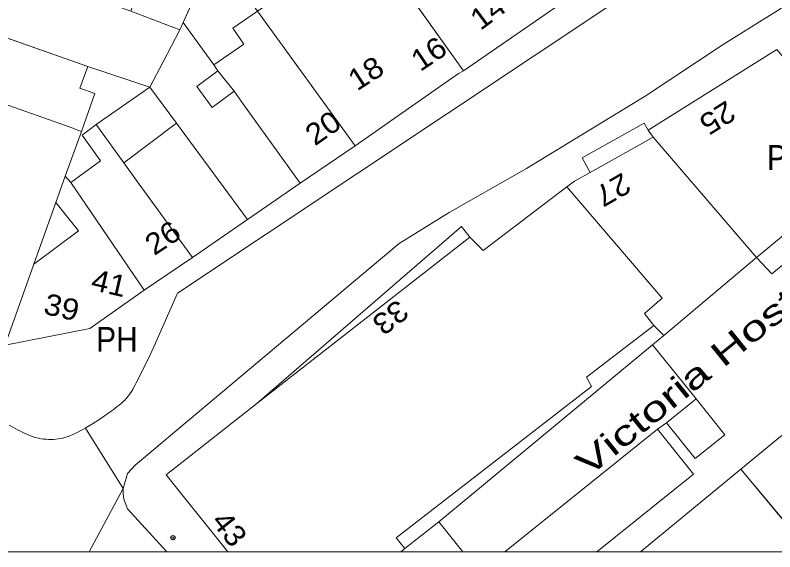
# Model space of a CAD drawing. Extents: x 528790 to 529292, y 179350 to 179856.
# Drawn here: x 529183.9 to 529237.6, y 179356 to 179393.9 of the extents above; entities that cross this region are included whole.
import ezdxf

# ---------------------------------------------------------------- set-up
doc = ezdxf.new("R2010")
doc.units = 0
doc.header["$LTSCALE"] = 0.6
doc.header["$PDMODE"] = 32
doc.header["$PDSIZE"] = 0.3
for name, color, linetype, lineweight in [('1', 7, 'Continuous', 13), ('2', 7, 'Continuous', 13), ('7', 7, 'Continuous', 13)]:
    doc.layers.add(name, color=color, linetype=linetype, lineweight=lineweight)
doc.layers.add('3', color=7, linetype='Continuous')
doc.layers.add('5', color=7, linetype='Continuous')

msp = doc.modelspace()

# ---------------------------------------------------------------- linework, layer by layer
at = {"layer": '1'}
for points in [[(529239.4, 179406.6), (529234.8, 179403.4), (529226.7, 179397.75), (529223, 179395.15), (529215.55, 179390), (529215.2, 179389.8), (529207.9, 179384.7), (529204, 179382.05), (529200.3, 179379.5), (529196.4, 179376.8), (529193, 179374.5), (529189.15, 179371.8), (529183.05, 179370.6)], [(529183.458, 179364.958), (529183.932, 179364.699), (529184.095, 179364.619), (529184.258, 179364.538), (529184.42, 179364.457), (529184.584, 179364.378), (529184.748, 179364.302), (529184.914, 179364.23), (529185.082, 179364.166), (529185.253, 179364.109), (529185.533, 179364.039), (529185.705, 179364.009), (529185.879, 179363.986), (529186.053, 179363.97), (529186.228, 179363.96), (529186.403, 179363.958), (529186.578, 179363.963), (529186.752, 179363.975), (529186.926, 179363.994), (529187.144, 179364.029), (529187.611, 179364.159), (529188.058, 179364.351), (529188.837, 179364.767), (529188.885, 179364.793), (529189.344, 179365.053), (529189.791, 179365.334), (529190.648, 179365.95), (529190.79, 179366.06), (529190.932, 179366.169), (529191.074, 179366.279), (529191.215, 179366.39), (529191.353, 179366.504), (529191.487, 179366.622), (529191.615, 179366.745), (529191.738, 179366.875), (529191.879, 179367.045), (529191.984, 179367.189), (529192.084, 179367.338), (529192.177, 179367.49), (529192.264, 179367.647), (529192.344, 179367.807), (529192.418, 179367.97), (529193.277, 179369.635), (529193.664, 179370.506), (529195.35, 179374.3), (529233.5, 179399.7)], [(529233.5, 179399.7), (529195.35, 179374.3), (529193.664, 179370.506), (529193.277, 179369.635), (529192.418, 179367.97), (529192.344, 179367.807), (529192.264, 179367.647), (529192.177, 179367.49), (529192.084, 179367.338), (529191.984, 179367.189), (529191.879, 179367.045), (529191.738, 179366.875), (529191.615, 179366.745), (529191.487, 179366.622), (529191.353, 179366.504), (529191.215, 179366.39), (529191.074, 179366.279), (529190.932, 179366.169), (529190.79, 179366.06), (529190.648, 179365.95), (529189.791, 179365.334), (529189.344, 179365.053), (529188.885, 179364.793), (529188.837, 179364.767), (529191.5, 179360.5), (529191.8, 179361.55), (529192.35, 179362.15), (529211, 179377.8), (529214.55, 179380), (529220, 179383.1), (529228.4, 179388.2), (529233.9, 179391.85), (529237.9, 179394.35)], [(529237.9, 179394.35), (529233.9, 179391.85), (529228.4, 179388.2), (529220, 179383.1), (529214.55, 179380), (529211, 179377.8), (529192.35, 179362.15), (529191.8, 179361.55), (529191.5, 179360.5), (529191.5, 179360.15), (529191.55, 179359.75), (529191.8, 179359.05), (529194.591, 179356.024), (529198.897, 179356.024), (529194.55, 179361.45), (529200.95, 179366.5), (529215.4, 179379), (529216, 179378.25), (529216.95, 179377.3), (529222.85, 179381.8), (529223.4, 179382.2), (529224.512, 179382.821), (529223.941, 179383.844), (529228.325, 179386.292), (529228.6, 179385.8), (529237.7, 179391.5)], [(529179.179, 179356.024), (529189.094, 179356.024), (529191.5, 179360.5), (529188.837, 179364.767), (529188.058, 179364.351), (529187.611, 179364.159), (529187.144, 179364.029), (529186.926, 179363.994), (529186.752, 179363.975), (529186.578, 179363.963), (529186.403, 179363.958), (529186.228, 179363.96), (529186.053, 179363.97), (529185.879, 179363.986), (529185.705, 179364.009), (529185.533, 179364.039), (529185.253, 179364.109), (529185.082, 179364.166), (529184.914, 179364.23), (529184.748, 179364.302), (529184.584, 179364.378), (529184.42, 179364.457), (529184.258, 179364.538), (529184.095, 179364.619), (529183.932, 179364.699), (529183.458, 179364.958)]]:
    msp.add_lwpolyline(points, dxfattribs=at)
for points in [[(529208.95, 179399.25), (529215.55, 179390), (529223, 179395.15), (529218.15, 179401.95), (529218.25, 179402.05), (529216.35, 179402.85), (529215, 179403.45)], [(529195.75, 179393.4), (529198, 179398.4), (529198.45, 179399.4), (529195.55, 179400.501), (529194.427, 179400.927), (529192.05, 179394.2), (529195.5, 179392.9)], [(529215.55, 179390), (529208.95, 179399.25), (529208.6, 179399.55), (529203.45, 179395.9), (529201, 179394.2), (529207.9, 179384.7), (529215.2, 179389.8)], [(529194.322, 179390.628), (529195.5, 179392.9), (529192.05, 179394.2), (529181.1, 179398.15), (529180.5, 179396.45), (529179.5, 179393.65), (529189, 179390.3), (529193.4, 179388.85)], [(529200.033, 179391.89), (529199.25, 179393), (529201, 179394.2), (529198, 179398.4), (529195.75, 179393.4), (529197.901, 179390.415)], [(529207.9, 179384.7), (529201, 179394.2), (529199.25, 179393), (529200.033, 179391.89), (529197.901, 179390.415), (529198.2, 179390), (529199.35, 179388.55), (529200.019, 179387.614), (529204, 179382.05)], [(529189.51, 179388.389), (529188.452, 179388.767), (529189, 179390.3), (529179.5, 179393.65), (529178.9, 179391.9), (529177.1, 179386.8), (529182.05, 179385.2), (529182.95, 179387.7), (529187.5, 179386.1), (529188.55, 179385.7)], [(529196.7, 179388.9), (529198.2, 179390), (529197.901, 179390.415), (529195.75, 179393.4), (529195.5, 179392.9), (529194.322, 179390.628), (529193.4, 179388.85), (529195.283, 179386.294), (529196.201, 179385.051), (529200.3, 179379.5), (529204, 179382.05), (529200.019, 179387.614), (529199.35, 179388.55), (529197.8, 179387.4)], [(529244.4, 179383.55), (529238.902, 179390.073), (529237.7, 179391.5), (529228.6, 179385.8), (529228.95, 179385.3), (529236.25, 179376.8), (529240.569, 179380.377)], [(529189.9, 179383.65), (529188.6, 179385.45), (529189.6, 179386.2), (529193.4, 179388.85), (529189, 179390.3), (529188.452, 179388.767), (529189.51, 179388.389), (529188.55, 179385.7), (529187.4, 179382.55), (529187.8, 179382.1)], [(529198.2, 179390), (529196.7, 179388.9), (529197.8, 179387.4), (529199.35, 179388.55)], [(529195.283, 179386.294), (529193.4, 179388.85), (529189.6, 179386.2), (529191.551, 179383.495)], [(529187.4, 179382.55), (529188.55, 179385.7), (529187.5, 179386.1), (529182.95, 179387.7), (529182.05, 179385.2), (529177.1, 179386.8), (529172.8, 179374.55), (529173.4, 179374.4), (529178, 179372.9), (529183.3, 179371.05), (529185.2, 179376.35), (529186.75, 179380.7)], [(529196.4, 179376.8), (529192.452, 179382.251), (529191.551, 179383.495), (529189.6, 179386.2), (529188.6, 179385.45), (529189.9, 179383.65), (529187.8, 179382.1), (529193, 179374.5)], [(529200.3, 179379.5), (529196.201, 179385.051), (529195.283, 179386.294), (529191.551, 179383.495), (529192.452, 179382.251), (529196.4, 179376.8)], [(529224.512, 179382.821), (529228.95, 179385.3), (529228.6, 179385.8), (529228.325, 179386.292), (529223.941, 179383.844)], [(529236.25, 179376.8), (529228.95, 179385.3), (529224.512, 179382.821), (529223.4, 179382.2), (529222.85, 179381.8), (529229.6, 179373.95), (529228.35, 179372.85), (529229, 179372), (529229.7, 179371.3)], [(529241.6, 179379.15), (529245.592, 179382.438), (529244.4, 179383.55), (529240.569, 179380.377), (529236.25, 179376.8), (529237.35, 179375.65)], [(529186.75, 179380.7), (529188.35, 179378.7), (529185.2, 179376.35), (529183.3, 179371.05), (529183.05, 179370.6), (529189.15, 179371.8), (529193, 179374.5), (529187.8, 179382.1), (529187.4, 179382.55)], [(529211.136, 179356.024), (529211.4, 179356.25), (529210.8, 179357), (529224.6, 179367.7), (529224.25, 179368.35), (529229, 179372), (529228.35, 179372.85), (529229.6, 179373.95), (529222.85, 179381.8), (529216.95, 179377.3), (529216, 179378.25), (529200.95, 179366.5), (529194.55, 179361.45), (529198.897, 179356.024)], [(529185.2, 179376.35), (529188.35, 179378.7), (529186.75, 179380.7)], [(529216, 179378.25), (529215.4, 179379), (529200.95, 179366.5)], [(529247.386, 179356.024), (529255.4, 179362.6), (529256.1, 179363.5), (529241.6, 179379.15), (529237.35, 179375.65), (529236.25, 179376.8), (529229.7, 179371.3), (529228.916, 179370.651), (529231.986, 179366.824), (529234.023, 179364.285), (529231.93, 179362.606), (529229.893, 179365.145), (529229.26, 179364.682), (529231.811, 179361.502), (529224.98, 179356.024), (529228.068, 179356.024), (529235.15, 179361.85), (529245.4, 179370.3), (529251.4, 179363.45), (529242.36, 179356.024)], [(529229.7, 179371.3), (529229, 179372), (529224.25, 179368.35), (529224.6, 179367.7), (529210.8, 179357), (529211.4, 179356.25), (529213.8, 179358.15), (529228.916, 179370.651)], [(529215.504, 179356.024), (529218.463, 179356.024), (529229.26, 179364.682), (529229.893, 179365.145), (529231.986, 179366.824), (529228.916, 179370.651), (529213.8, 179358.15)], [(529240.012, 179356.024), (529242.36, 179356.024), (529251.4, 179363.45), (529245.4, 179370.3), (529235.15, 179361.85)], [(529229.893, 179365.145), (529231.93, 179362.606), (529234.023, 179364.285), (529231.986, 179366.824)], [(529218.463, 179356.024), (529224.98, 179356.024), (529231.811, 179361.502), (529229.26, 179364.682)], [(529228.068, 179356.024), (529240.012, 179356.024), (529235.15, 179361.85)], [(529194.591, 179356.024), (529191.8, 179359.05), (529191.55, 179359.75), (529191.5, 179360.15), (529191.5, 179360.5), (529189.094, 179356.024)], [(529215.504, 179356.024), (529213.8, 179358.15), (529211.4, 179356.25), (529211.136, 179356.024)]]:
    msp.add_lwpolyline(points, close=True, dxfattribs=at)
at = {"layer": '2'}
for p, q in [((529208.95, 179399.25), (529215.55, 179390)), ((529198, 179398.4), (529195.75, 179393.4)), ((529223, 179395.15), (529215.55, 179390)), ((529192.05, 179394.2), (529195.5, 179392.9)), ((529201, 179394.2), (529207.9, 179384.7)), ((529179.5, 179393.65), (529189, 179390.3)), ((529195.5, 179392.9), (529195.75, 179393.4)), ((529195.75, 179393.4), (529197.901, 179390.415)), ((529237.7, 179391.5), (529228.6, 179385.8)), ((529189, 179390.3), (529193.4, 179388.85)), ((529197.901, 179390.415), (529198.2, 179390)), ((529199.35, 179388.55), (529198.2, 179390)), ((529189.6, 179386.2), (529193.4, 179388.85)), ((529195.283, 179386.294), (529193.4, 179388.85)), ((529189.6, 179386.2), (529191.551, 179383.495)), ((529191.551, 179383.495), (529195.283, 179386.294)), ((529188.55, 179385.7), (529187.4, 179382.55)), ((529228.6, 179385.8), (529228.95, 179385.3)), ((529228.95, 179385.3), (529224.512, 179382.821)), ((529236.25, 179376.8), (529228.95, 179385.3)), ((529207.9, 179384.7), (529204, 179382.05)), ((529187.4, 179382.55), (529186.75, 179380.7)), ((529187.4, 179382.55), (529187.8, 179382.1)), ((529187.8, 179382.1), (529193, 179374.5)), ((529204, 179382.05), (529200.3, 179379.5)), ((529186.75, 179380.7), (529185.2, 179376.35)), ((529200.3, 179379.5), (529196.4, 179376.8)), ((529200.95, 179366.5), (529216, 179378.25)), ((529196.4, 179376.8), (529193, 179374.5)), ((529229.7, 179371.3), (529236.25, 179376.8)), ((529185.2, 179376.35), (529183.3, 179371.05)), ((529229, 179372), (529229.7, 179371.3)), ((529228.916, 179370.651), (529229.7, 179371.3)), ((529213.8, 179358.15), (529228.916, 179370.651)), ((529231.986, 179366.824), (529228.916, 179370.651)), ((529229.893, 179365.145), (529231.986, 179366.824)), ((529191.5, 179360.5), (529188.837, 179364.767)), ((529229.26, 179364.682), (529218.463, 179356.024)), ((529229.26, 179364.682), (529229.893, 179365.145)), ((529228.068, 179356.024), (529235.15, 179361.85)), ((529235.15, 179361.85), (529240.012, 179356.024)), ((529189.094, 179356.024), (529191.5, 179360.5)), ((529211.4, 179356.25), (529213.8, 179358.15)), ((529213.8, 179358.15), (529215.504, 179356.024)), ((529211.136, 179356.024), (529211.4, 179356.25))]:
    msp.add_line(p, q, dxfattribs=at)
for points in [[(529191.5, 179360.5), (529191.8, 179361.55), (529192.35, 179362.15), (529211, 179377.8), (529214.55, 179380), (529220, 179383.1), (529228.4, 179388.2), (529233.9, 179391.85), (529237.9, 179394.35), (529249.7, 179402.75)], [(529188.837, 179364.767), (529188.885, 179364.793), (529189.344, 179365.053), (529189.791, 179365.334), (529190.648, 179365.95), (529190.79, 179366.06), (529190.932, 179366.169), (529191.074, 179366.279), (529191.215, 179366.39), (529191.353, 179366.504), (529191.487, 179366.622), (529191.615, 179366.745), (529191.738, 179366.875), (529191.879, 179367.045), (529191.984, 179367.189), (529192.084, 179367.338), (529192.177, 179367.49), (529192.264, 179367.647), (529192.344, 179367.807), (529192.418, 179367.97), (529193.277, 179369.635), (529193.664, 179370.506), (529195.35, 179374.3), (529233.5, 179399.7)], [(529197.901, 179390.415), (529200.033, 179391.89), (529199.25, 179393), (529201, 179394.2)], [(529193.4, 179388.85), (529194.322, 179390.628), (529195.5, 179392.9)], [(529189, 179390.3), (529188.452, 179388.767), (529189.51, 179388.389), (529188.55, 179385.7)], [(529198.2, 179390), (529196.7, 179388.9), (529197.8, 179387.4), (529199.35, 179388.55)], [(529215.55, 179390), (529215.2, 179389.8), (529207.9, 179384.7)], [(529199.35, 179388.55), (529200.019, 179387.614), (529204, 179382.05)], [(529177.1, 179386.8), (529182.05, 179385.2), (529182.95, 179387.7), (529187.5, 179386.1), (529188.55, 179385.7)], [(529187.8, 179382.1), (529189.9, 179383.65), (529188.6, 179385.45), (529189.6, 179386.2)], [(529200.3, 179379.5), (529196.201, 179385.051), (529195.283, 179386.294)], [(529224.512, 179382.821), (529223.941, 179383.844), (529228.325, 179386.292), (529228.6, 179385.8)], [(529191.551, 179383.495), (529192.452, 179382.251), (529196.4, 179376.8)], [(529236.25, 179376.8), (529240.569, 179380.377), (529244.4, 179383.55)], [(529224.512, 179382.821), (529223.4, 179382.2), (529222.85, 179381.8)], [(529222.85, 179381.8), (529216.95, 179377.3), (529216, 179378.25)], [(529222.85, 179381.8), (529229.6, 179373.95), (529228.35, 179372.85), (529229, 179372)], [(529186.75, 179380.7), (529188.35, 179378.7), (529185.2, 179376.35)], [(529216, 179378.25), (529215.4, 179379), (529200.95, 179366.5)], [(529236.25, 179376.8), (529237.35, 179375.65), (529241.6, 179379.15)], [(529193, 179374.5), (529189.15, 179371.8), (529183.05, 179370.6)], [(529211.4, 179356.25), (529210.8, 179357), (529224.6, 179367.7), (529224.25, 179368.35), (529229, 179372)], [(529235.15, 179361.85), (529245.4, 179370.3), (529251.4, 179363.45), (529242.36, 179356.024)], [(529231.986, 179366.824), (529234.023, 179364.285), (529231.93, 179362.606), (529229.893, 179365.145)], [(529200.95, 179366.5), (529194.55, 179361.45), (529198.897, 179356.024)], [(529183.458, 179364.958), (529183.932, 179364.699), (529184.095, 179364.619), (529184.258, 179364.538), (529184.42, 179364.457), (529184.584, 179364.378), (529184.748, 179364.302), (529184.914, 179364.23), (529185.082, 179364.166), (529185.253, 179364.109), (529185.533, 179364.039), (529185.705, 179364.009), (529185.879, 179363.986), (529186.053, 179363.97), (529186.228, 179363.96), (529186.403, 179363.958), (529186.578, 179363.963), (529186.752, 179363.975), (529186.926, 179363.994), (529187.144, 179364.029), (529187.611, 179364.159), (529188.058, 179364.351), (529188.837, 179364.767)], [(529224.98, 179356.024), (529231.811, 179361.502), (529229.26, 179364.682)], [(529194.591, 179356.024), (529191.8, 179359.05), (529191.55, 179359.75), (529191.5, 179360.15), (529191.5, 179360.5)]]:
    msp.add_lwpolyline(points, dxfattribs=at)
at = {"layer": '3'}
msp.add_point((529195.027, 179357.021), dxfattribs=at)
at = {"layer": '7'}
msp.add_lwpolyline([(528790.22, 179356.024), (529290.22, 179356.024), (529290.22, 179856.024), (528790.22, 179856.024)], close=True, dxfattribs=at)

# ---------------------------------------------------------------- texts
at = {"layer": '5'}
for s, height, rotation, width, p in [('14', 1.5, 37, 1.1, (529216.75, 179392.8)), ('16', 1.5, 34, 1.1, (529212.5, 179389.9)), ('18', 1.5, 33, 1.1, (529208.03, 179388.53)), ('25', 1.5, 212, 1.1, (529234.15, 179387.95)), ('20', 1.5, 35, 1.1, (529205.05, 179384.65)), ('27', 1.5, 210, 1.1, (529226.8, 179382.85)), ('26', 1.5, 34, 1.1, (529193.7, 179376.9)), ('Victoria Hostel', 1.75, 39, 1.45, (529224.38, 179361.26)), ('41', 1.5, 347, 1.1, (529189.15, 179374.55)), ('39', 1.5, 347, 1.1, (529185.8, 179372.85)), ('33', 1.5, 218, 1.1, (529210.91, 179373.92)), ('43', 1.5, 308, 1.1, (529197.67, 179358.16))]:
    msp.add_text(s, height=height, rotation=rotation, dxfattribs=dict(at, width=width)).set_placement(p)
at = {"layer": '5', "width": 0.9}
for p in [(529237, 179383), (529189.6, 179370.15)]:
    msp.add_text('PH', height=1.75, dxfattribs=at).set_placement(p)

doc.saveas('drawing.dxf')
